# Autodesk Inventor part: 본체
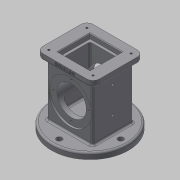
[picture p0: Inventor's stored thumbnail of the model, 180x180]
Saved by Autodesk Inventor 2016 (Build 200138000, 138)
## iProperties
Created: 2017-08
Part Number: 본체
Material: 알루미늄 6061
Document SubType Name: Modeling
Designer: mduedu
Density: 2.71 g/cm^3
Appearance: 기본값
Mass: 988.221 g
Surface Area: 743.905 cm^2
Volume: 364.657 cm^3
Author: mduedu
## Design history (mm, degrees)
sketch "스케치7"
  geometry: C1 r 62.5 at (0, 0); C2 r 4.5 at (50, 0); C3 r 4.5 at (0, -50); C4 r 4.5 at (-50, 0); C5 r 4.5 at (0, 50); A1 r 50 centre (0, 0) between (50, 0) and (0, -50); 1 further point
  constraints: 6 centre point, 4 point on circle, 2 coincident
  dimensions: "d62" = 125 diameter of C1; "d70" = 100 diameter of A1; "d71" = 9 diameter of C2; "d72" = 9 diameter of C3; "d73" = 9 diameter of C4; "d74" = 9 diameter of C5
node "작업 평면3"
extrude "돌출6" new body sketch "스케치7" distance "d77" = 10; taper "d78" = 0 deg
sketch "스케치9"
  geometry: L1 (-37, -33)-(37, -33); L2 (37, -33)-(37, 33); L3 (37, 33)-(-37, 33); L4 (-37, 33)-(-37, -33); L5 (-37, -33)-(37, 33); L6 (37, -33)-(-37, 33); C1 r 62.5 at (0, 0) reference
  constraints: 12 end point, 2 midpoint, 2 parallel, 1 horizontal, 1 perpendicular
  dimensions: "d79" = 74 distance of L3.end L2.end; "d80" = 66 distance of L1.end L2.end
extrude "돌출7" join sketch "스케치9" distance "d82" = 88; taper "d83" = 0 deg
sketch "스케치10"
  geometry: L1 (-36, -41)-(36, -41); L2 (46, -31)-(46, 31); L3 (36, 41)-(-36, 41); L4 (-46, 31)-(-46, -31); A1 r 10 centre (-36, 31) between (-36, 41) and (-46, 31); A2 r 10 centre (-36, -31) between (-46, -31) and (-36, -41); A3 r 10 centre (36, -31) between (36, -41) and (46, -31); A4 r 10 centre (36, 31) between (46, 31) and (36, 41); 1 further point
  constraints: 8 end point, 8 point on circle, 8 tangent, 4 centre point, 3 equal radius, 2 parallel, 1 horizontal, 1 perpendicular
  dimensions: "d86" = 10 radius of A1
extrude "돌출8" join sketch "스케치10" distance "d87" = 10; taper "d88" = 0 deg
sketch "스케치11"
  geometry: L1 (-25.5, -10)-(99.5, -10) reference; C1 r 35 at (37, 44); 2 further points
  constraints: 1 centre point, 1 midpoint, 1 vertical alignment
  dimensions: "d89" = 70 diameter of C1; "d90" = 54 distance from line of L1 C1.centre
extrude "돌출9" cut sketch "스케치11" distance "d91" = 3; taper "d92" = 0 deg
hole "구멍5" diameter "d95" = 48; stored, may be unused: countersink angle "d99" = 90 deg, drill point angle "d101" = 118 deg; dims "d93" = 10, "d94" = 10, "d96" = 6, "d97" = 4, "d98" = 2, "d100" = 8
sketch "스케치12"
  geometry: L1 (26, -26)-(-26, -26); L2 (-26, -26)-(-26, 26); L3 (-26, 26)-(26, 26); L4 (26, 26)-(26, -26); L5 (26, -26)-(-26, 26); L6 (-26, -26)-(26, 26); 1 further point
  constraints: 12 end point, 2 midpoint, 2 parallel, 1 horizontal, 1 perpendicular
  dimensions: "d102" = 52 distance of L2.end L3.end; "d103" = 52 distance of L1.end L2.end
extrude "돌출10" cut sketch "스케치12" distance "d104" = 8; taper "d105" = 0 deg
sketch "스케치13"
  geometry: L1 (19, -22)-(-19, -22); L2 (-22, -19)-(-22, 19); L3 (-19, 22)-(19, 22); L4 (22, 19)-(22, -19); L5 (22, -22)-(-22, 22); L6 (-22, -22)-(22, 22); A1 r 3 centre (19, -19) between (19, -22) and (22, -19); A2 r 3 centre (19, 19) between (22, 19) and (19, 22); A3 r 3 centre (-19, 19) between (-19, 22) and (-22, 19); A4 r 3 centre (-19, -19) between (-22, -19) and (-19, -22); 1 further point
  constraints: 12 end point, 8 point on circle, 8 point on line, 8 tangent, 4 centre point, 3 equal radius, 2 midpoint, 2 parallel, 1 horizontal, 1 perpendicular
  dimensions: "d106" = 44 distance of L5.end L6.end; "d107" = 44 distance of L6.start L5.end; "d140" = 3 radius of A1
extrude "돌출11" cut sketch "스케치13" distance "d108" = 74; taper "d109" = 0 deg
sketch "스케치14"
  geometry: C1 r 62.5 at (0, 0) reference; C2 r 28 at (0, 0)
  constraints: 1 centre point, 1 coincident
  dimensions: "d110" = 56 diameter of C2
extrude "돌출12" cut sketch "스케치14" distance "d111" = 18; taper "d112" = -10 deg
sketch "스케치15"
  geometry: L1 (-36, -31)-(36, -31); L2 (36, -31)-(36, 31); L3 (36, 31)-(-36, 31); L4 (-36, 31)-(-36, -31); L5 (-36, -31)-(36, 31); L6 (36, -31)-(-36, 31); A1 r 10 centre (-36, -31) between (-46, -31) and (-36, -41) reference; A2 r 10 centre (36, -31) between (36, -41) and (46, -31) reference; A3 r 10 centre (36, 31) between (46, 31) and (36, 41) reference; 1 further point
  constraints: 12 end point, 2 midpoint, 2 parallel, 1 horizontal, 1 perpendicular
  dimensions: "d113" = 72 distance of L3.end L2.end (derived); "d114" = 62 distance of L2.end L1.end (derived)
hole "구멍6" sketch "스케치15" at (-36, 31), (-36, -31), (36, -31), (36, 31) diameter "d115" = 3.242; stored, may be unused: countersink angle "d119" = 90 deg, drill point angle "d121" = 118 deg; dims "d116" = 4, "d117" = 4, "d118" = 2, "d120" = 6
sketch "스케치16"
  geometry: C1 r 35 at (0, 0) reference; C2 r 35 at (0, 0) reference; A1 r 29 centre (0, 0) between (0, 29) and (-29, 0); 3 further points
  constraints: 4 point on circle, 1 centre point, 1 coincident, 1 concentric
  dimensions: "d122" = 58 diameter of A1
hole "구멍7" sketch "스케치16" at (0, 29), (-29, 0), (0, -29), (29, 0) diameter "d123" = 3.242; stored, may be unused: countersink angle "d127" = 90 deg, drill point angle "d129" = 118 deg; dims "d124" = 4, "d125" = 4, "d126" = 2, "d128" = 6
sketch "스케치17"
  geometry: L1 (-29.5, -10)-(95.5, -10) reference; 4 further points
  constraints: 2 vertical alignment, 1 midpoint
  dimensions: "d130" = 43 distance of point (33, 27) point (33, 70); "d131" = 37 distance from line of L1 point (33, 27)
hole "구멍8" sketch "스케치17" at (33, 27), (33, 70) diameter "d132" = 4.134; stored, may be unused: countersink angle "d136" = 90 deg, drill point angle "d138" = 118 deg; dims "d133" = 10, "d134" = 4, "d135" = 2, "d137" = 23.25
fillet "모깎기6" dims "d139" = 3
fillet "모깎기7" dims "d141" = 3
chamfer "모따기3" distance "d142" = 1; stored, may be unused: second distance "d143" = 2, angle "d144" = 45 deg
sketch "스케치18"
  geometry: L1 (0, 0)-(72, 0) reference; L2 (-10, -7)-(-10, 0) reference; 2 further points
  constraints: 1 other
  dimensions: "d145" = 46 distance from line of L2 point (36, -4); "d146" = 4 distance from line of L1 point (36, -4)
feature "엠보싱1" sketch "스케치18" dims "d62" = 125, "d70" = 100, "d71" = 9, "d72" = 9, "d73" = 9, "d74" = 9, "d147" = 0.5, "d148" = 0
sketch "스케치19"
  geometry: L1 (36, 38)-(126, 38); L2 (126, 38)-(126, -118); L3 (126, -118)-(36, -118); L4 (36, -118)-(36, 38); 1 further point
  constraints: 8 end point, 2 parallel, 1 horizontal, 1 perpendicular
extrude "돌출13" cut sketch "스케치19" distance "d149" = 112.75; taper "d151" = 0 deg; dims "d150" = 57.125, "d152" = 0
node "솔리드3"
mirror "대칭1"
mirror "대칭2"
